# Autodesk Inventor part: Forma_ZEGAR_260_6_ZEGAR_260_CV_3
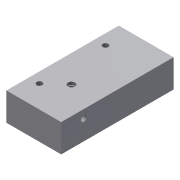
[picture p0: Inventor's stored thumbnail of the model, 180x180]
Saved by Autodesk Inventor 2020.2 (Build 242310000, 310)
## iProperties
Created: 2015-01
Part Number: Forma_ZEGAR_260_6_ZEGAR_260_CV_3
Material: Ogólny
Document SubType Name: Modeling
Designer: F.Stasiak
Density: 1 g/cm^3
Appearance: Domyślna
Catalog Web Link: www.expertbooks.pl
Manager: www.cadconsulting.pl
Company: Fabian Stasiak CAD Consulting
Author: F.Stasiak
Subject: Zbiór ćwiczeń. Autodesk Inventor 2020. Kurs Professional
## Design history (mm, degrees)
node "Forma_ZEGAR_260_4_ZEGAR_260_CV_Base"
feature "Rzeźbienie4"
feature "Gwint1" dims "d0" = 0, "d1" = 0
feature "Rzeźbienie6"
feature "Rzeźbienie8"
feature "Gwint3" dims "d4" = 0, "d5" = 0
feature "Rzeźbienie11"
feature "Bryła1::Forma_ZEGAR_260_4_ZEGAR_260_CV_Base"
tag "Bryła wyprowadzona1"
node "Bryła1"
feature "Forma_ZEGAR_260_4_ZEGAR_260_CV_Base_Bodies"
feature "Powierzchnia4"
body "Srf4"
feature "Powierzchnia6"
body "Srf6"
feature "Powierzchnia8"
body "Srf8"
feature "Powierzchnia11"
body "Srf11"
other parameters: "d10" = 0, "d11" = -26.4075, "d13" = 0, "d14" = -180 deg, "d15" = 0
